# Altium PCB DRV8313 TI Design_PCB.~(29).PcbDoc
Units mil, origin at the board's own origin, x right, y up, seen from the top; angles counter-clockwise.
Board outline 2200 x 1250 mil, 2 copper layers (Top Layer, Bottom Layer), stack 62 mil thick; 47 components, 31 nets, 131 pads, 80 vias.
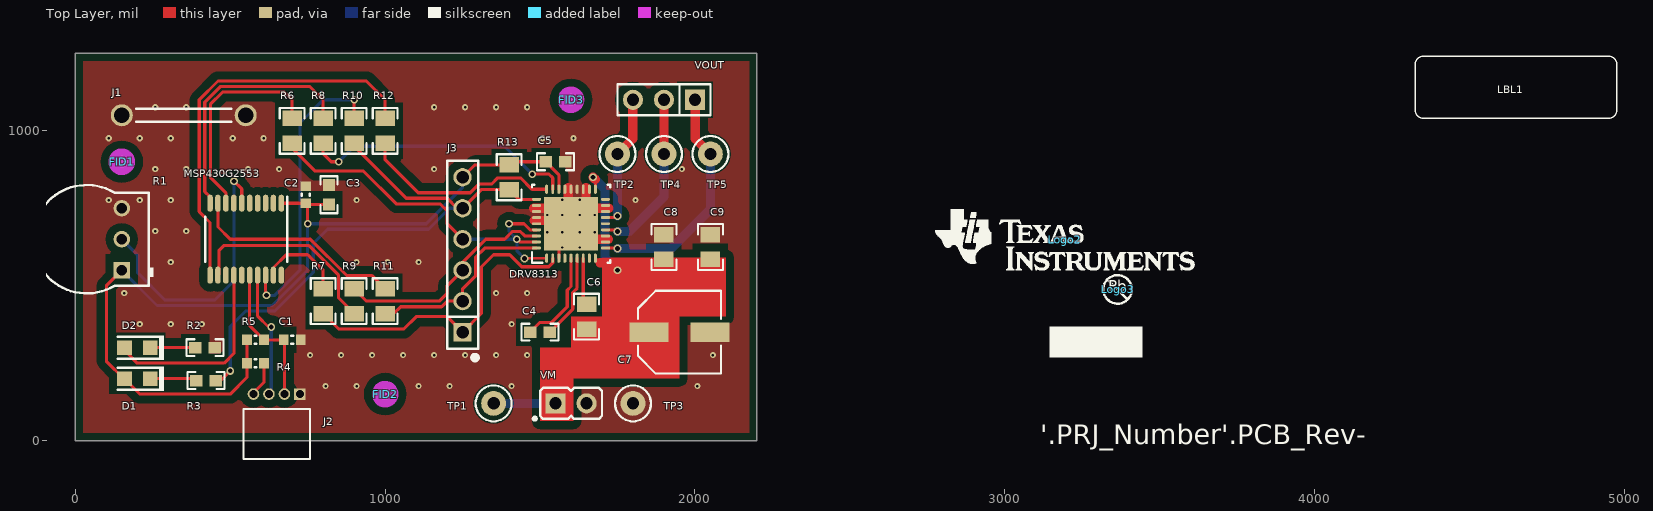
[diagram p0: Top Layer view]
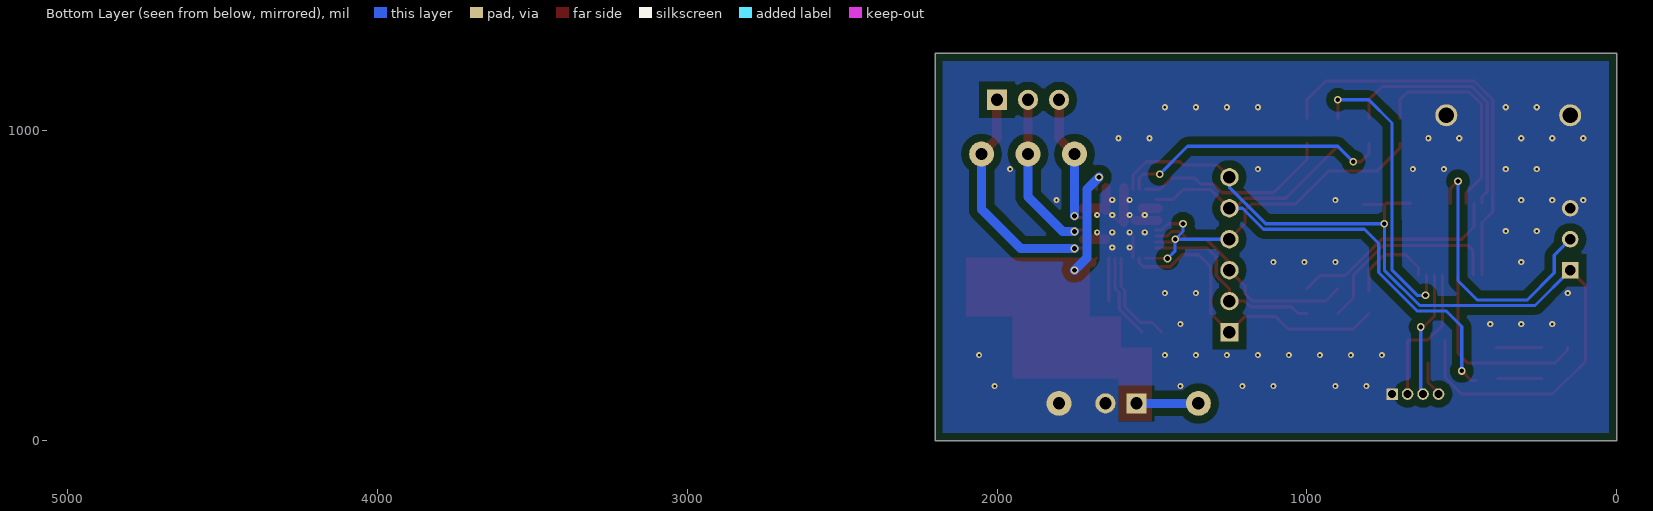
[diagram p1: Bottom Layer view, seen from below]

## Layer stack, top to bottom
Top Solder: solder mask 0.4, Solder Resist, Dk 3.5
Top Layer: signal copper 1.4
Dielectric1: core 59.2, FR-4, Dk 4.8
Bottom Layer: signal copper 1.4
Bottom Solder: solder mask 0.4, Solder Resist, Dk 3.5

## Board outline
0,0 2200,0 2200,1250 0,1250

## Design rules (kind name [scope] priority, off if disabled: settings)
AcuteAngle [All] p1: minimum=4.50000000000000E+0001 checktracksonly=FALSE
AssemblyTestPointUsage [All] p1: valid=2
BoardOutlineClearance BoardOutlineClearance_MountingHoles [OnCopper and InComponentClass('Mounting Holes')] p1: gap=40
BoardOutlineClearance BoardOutlineClearance_Poly [OnCopper and IsPoly] p2: gap=25
BoardOutlineClearance [OnCopper and Not InComponentClass('Logo') and not InComponentClass('FiducialMark') and not InRegion(1000,500,4000,800) and not InPoly] p3: gap=75
Clearance Clearance_Keepouts [((IsTrack Or IsArc) And Not InPoly) And IsFree and IsKeepOut vs ((IsTrack Or IsArc) And Not InPoly) And IsFree and IsKeepOut] p1: gap=0
Clearance Clearance_Poly [InPolygon] p2: gap=25
Clearance [All] p3: gap=7.87
ComponentClearance ComponentClearance_MountingHoles_FiducialMarks [InComponentClass('Mounting Holes') vs InComponentClass('FiducialMark')] p1: gap=50 collisioncheckmode=3 verticalgap=10 showdistances=FALSE
ComponentClearance ComponentClearance_Shunt [InComponentClass('Header') vs InComponentClass('Shunt')] p2: gap=0 collisioncheckmode=3 verticalgap=0 showdistances=FALSE
ComponentClearance ComponentClearance_Logo [InComponentClass('Logo')] p3: gap=50 collisioncheckmode=3 verticalgap=10 showdistances=FALSE
ComponentClearance ComponentClearance_ScrewToNut [(HasFootprint('NY PMS 440 0025 PH')) vs (HasFootprint('Keystone_1902C'))] p4: gap=5 collisioncheckmode=3 verticalgap=10 showdistances=FALSE
ComponentClearance ComponentClearance_MountingHoles [InComponentClass('Mounting Holes')] p5: gap=250 collisioncheckmode=3 verticalgap=100000 showdistances=FALSE
ComponentClearance ComponentClearance_SmallPassives [HasFootprint('0201*') or HasFootprint('0402*') or HasFootprint('0508') or HasFootprint('0603*') or HasFootprint('0612') or HasFootprint('0805*') or HasFootprint('0815*') or HasFootprint('0830*') or HasFootprint('1206*') or HasFootprint('1210*') or HasFootprint('1808*') or HasFootprint('1812*') or HasFootprint('1825*') or HasFootprint('2010*') or HasFootprint('2220*') or HasFootprint('2225*') or HasFootprint('2512*') or HasFootprint('2728*') or HasFootprint('3518*') vs HasFootprint('0201*') or HasFootprint('0402*') or HasFootprint('0508') or HasFootprint('0603*') or HasFootprint('0612') or HasFootprint('0805*') or HasFootprint('0815*') or HasFootprint('0830*') or HasFootprint('1206*') or HasFootprint('1210*') or HasFootprint('1808*') or HasFootprint('1812*') or HasFootprint('1825*') or HasFootprint('2010*') or HasFootprint('2220*') or HasFootprint('2225*') or HasFootprint('2512*') or HasFootprint('2728*') or HasFootprint('3518*')] p6: gap=14.96 collisioncheckmode=3 verticalgap=10 showdistances=FALSE
ComponentClearance ComponentClearance_THtoSMT [IsThruComponent vs IsSMTComponent] p7: gap=40 collisioncheckmode=3 verticalgap=30 showdistances=FALSE
ComponentClearance ComponentClearance_THtoTH [IsThruComponent vs IsThruComponent] p8: gap=30 collisioncheckmode=3 verticalgap=30 showdistances=FALSE
ComponentClearance [All] p9: gap=30 collisioncheckmode=3 verticalgap=10 showdistances=FALSE
DiffPairsRouting [All] p1: maxlimit=100 minlimit=10 mostfreqgap=10 toplayer_minwidth=15 toplayer_maxwidth=15 toplayer_prefwidth=15 bottomlayer_minwidth=15 bottomlayer_maxwidth=15 bottomlayer_prefwidth=15 maxuncoupledlength=1000
FabricationTestPointUsage TestPointUsage [All] p1: valid=2 allowmultiple=FALSE
FabricationTestpoint Testpoint [All] p1: side=3 testpointundercomponent=TRUE minsize=40 maxsize=100 preferedsize=60 minholesize=0 maxholesize=40 preferedholesize=32 testpointgrid=1 allowsidetop=TRUE allowsidebottom=TRUE usegrid=TRUE gridtolerance=0.01
FanoutControl Fanout_LCC [IsLCC] p1: bgadir=Out bgaviamode=Centered fanoutstyle=Auto fanoutdirection=Alternating viagrid=1 // Fanout_LCC (Default Rule)
FanoutControl Fanout_BGA [IsBGA] p2: bgadir=Out bgaviamode=Centered fanoutstyle=Auto fanoutdirection=Alternating viagrid=1 // Fanout_BGA (Default Rule)
FanoutControl Fanout_Default [All] p4: bgadir=Out bgaviamode=Centered fanoutstyle=Auto fanoutdirection=Alternating viagrid=1 // Fanout_Default (Default Rule)
FanoutControl Fanout_Small [(CompPinCount < 5)] p5: bgadir=Out bgaviamode=Centered fanoutstyle=Auto fanoutdirection=OutThenIn viagrid=1 // Fanout_Small (Default Rule)
HoleSize [All] p1: absolutevalues=TRUE maxlimit=251 minlimit=7.87 maxpercent=80.000 minpercent=20.000
MinimumAnnularRing MinimumAnnularRing_ThermalPadVias [IsVia and InAnyComponent] p1: minimumring=5.91
MinimumAnnularRing [All] p2: minimumring=8
MinimumSolderMaskSliver MinimumSolderMaskSliver_Logo [InComponentClass('Logo') vs InComponentClass('Logo')] p1: minsoldermaskwidth=0.7
MinimumSolderMaskSliver [All] p2: minsoldermaskwidth=3.94
PlaneConnect [All] p1: planeconnectstyle=Relief reliefexpansion=10 reliefentries=4 reliefconductorwidth=10 reliefairgap=10
PolygonConnect [All] p1: connectstyle=Direct reliefconductorwidth=10 reliefentries=4 polygonreliefangle="90 Angle" airgapwidth=10
RoutingVias ThermalPadVias [IsVia and InAnyComponent] p1: holewidth=7.87 width=19.68 viastyle="Through Hole" minholewidth=7.87 minwidth=19.68 maxholewidth=12.99 maxwidth=23.62
RoutingVias [All] p2: holewidth=16 width=34 viastyle="Through Hole" minholewidth=7.87 minwidth=26 maxholewidth=40 maxwidth=65
SilkToBoardRegionClearance [Not ((IsComment or IsDesignator) And (Hide <> 'False')) and not InRegion(1000,500,4000,800)] p1:
SilkToSilkClearance SilkToSilkClearance_Pb-FreeLogo [(HasFootprint('Pb-Free_Overlay_Medium') OR HasFootprint('Pb-Free_Overlay_Small')) vs (HasFootprint('Pb-Free_Overlay_Medium') OR HasFootprint('Pb-Free_Overlay_Small'))] p1: silktosilkclearance=0
SilkToSilkClearance [All] p2: silktosilkclearance=4
SilkToSolderMaskClearance SilkToComponentPadClearance [IsPad and InAnycomponent] p1: minsilkscreentomaskgap=5 clearancetoexposedcopper=TRUE
SilkToSolderMaskClearance "Silk to Solder Mask Opening" [All] p2: minsilkscreentomaskgap=4 clearancetoexposedcopper=FALSE
SolderMaskExpansion [All] p1: expansion=1.97
Width [All] p1: maxlimit=100 minlimit=6 preferedwidth=10 checkconnectedcopper=TRUE
15 further rules are at their usual default settings.

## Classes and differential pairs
component class Logo: Logo1
component class FiducialMark: FID1 FID2 FID3
component class AssemblyNote: ZZ1 ZZ2 ZZ3 ZZ4
component class Label: LBL1
component class Header: J3 J? VM VOUT

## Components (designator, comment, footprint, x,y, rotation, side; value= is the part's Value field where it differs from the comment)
C1 "GRM188R71C102KA01D" 0603L 700,325 r0 top (schematic designator C7)
C2 "C0603C104K8RACTU" 0603L 743.68,793.5 r90 top (schematic designator C4)
C3 "GCM188R71C474KA55D" 0603 818.68,793.5 r90 top (schematic designator C9)
C4 "0.01uF" 0603 1500,350 r0 top (schematic designator C6)
C5 "GCM188R71C474KA55D" 0603 1550,900 r0 top (schematic designator C8)
C6 "C2012X5R2A104K125AA" 0805_HV 1650,400 r270 top (schematic designator C2)
C7 "EEE-FK1K100XP" SM_RADIAL_D8 1950,350 r0 top (schematic designator C5)
C8 "C2012X5R2A104K125AA" 0805_HV 1900,625 r270 top (schematic designator C1)
C9 "C2012X5R2A104K125AA" 0805_HV 2050,625 r90 top (schematic designator C2)
D1 "LTST-C170KRKT" LED_LTST-C170_Red 200,200 r0 top
D2 "LTST-C170KGKT" LTST-C170KGKT_Green 200,300 r0 top (schematic designator D3)
DRV8313 "DRV8313RHHR" RHH0036C 1600,700 r90 top (schematic designator U?)
FID1 "Fiducial" Fiducial10-20 150,900 r0 top
FID2 "Fiducial" Fiducial10-20 1000,150 r0 top
FID3 "Fiducial" Fiducial10-20 1600,1100 r0 top
J1 "D3082-05" Harwin_D3082-05 350,1050 r0 top (schematic designator J2)
J2 "851-43-004-20-001000" CONN_851-43-004-20-001000 650,150 r0 top (schematic designator J4)
J3 "PEC06SAAN" Sullins_PEC06SAAN 1250,600 r90 top (schematic designator J5)
LBL1 "Size: 0.65\" x 0.20 \"" Label_650x200 4650,1140.66 r0 top
Logo1 "FCC disclaimer" FCC_disclaimer 2350,3380 r0 top (schematic designator Logo3)
Logo2 "Texas Instruments" TI_Stacked_Overlay_Small 3193.98,647.98 r0 top (schematic designator Logo1)
Logo3 "Pb-Free Symbol" Pb-Free_Overlay_Small 3363.98,487.98 r0 top (schematic designator Logo2)
MSP430G2553 "MSP430G2553IPW20R" PW0020A_N 550,650 r270 top (schematic designator U2)
R1 "3352T-1-503LF" Bourns_3352T 150,650 r90 top (schematic designator R6)
R2 "CRCW0603330RJNEA" 0603 418.5,300 r0 top (schematic designator R3)
R3 "CRCW0603330RJNEA" 0603 421.95,193.68 r0 top (schematic designator R1)
R4 "CRCW06030000Z0EA" 0603L 581.3,250 r180 top (schematic designator R9)
R5 "CRCW060347K0JNEA" 0603L 581.3,325 r180 top (schematic designator R8)
R6 "ERJ-6GEY0R00V" 0805_HV 700,1000 r270 top (schematic designator R7)
R7 "ERJ-6GEY0R00V" 0805_HV 800,450 r270 top (schematic designator R12)
R8 "ERJ-6GEY0R00V" 0805_HV 800,1000 r270 top (schematic designator R16)
R9 "ERJ-6GEY0R00V" 0805_HV 900,450 r90 top (schematic designator R14)
R10 "ERJ-6GEY0R00V" 0805_HV 900,1000 r270 top (schematic designator R5)
R11 "ERJ-6GEY0R00V" 0805_HV 1000,450 r270 top (schematic designator R13)
R12 "ERJ-6GEY0R00V" 0805_HV 1000,1000 r270 top (schematic designator R15)
R13 "CRCW080510K0JNEA" 0805_HV 1400,850 r90 top (schematic designator R4)
TP1 "5000" Keystone5000 1350,120 r0 top
TP2 "5002" Keystone5002 1750,925 r0 top (schematic designator TP17)
TP3 "5001" Keystone5001 1800,120 r0 top (schematic designator TP2)
TP4 "5002" Keystone5002 1900,925 r0 top (schematic designator TP16)
TP5 "5002" Keystone5002 2050,925 r0 top (schematic designator TP15)
VM "PBC02SAAN" Sullins_PBC02SAAN 1600,120 r90 top (schematic designator J?)
VOUT "PBC03SAAN" PBC03SAAN 1900,1100 r180 top (schematic designator J?)
ZZ1 "These assemblies must comply with workmanship standards IPC-A-610 Class 2, unless otherwise specified." AssemblyNote 355,7262 r0 top (schematic designator ZZ4)
ZZ2 "These assemblies must be clean and free from flux and all contaminants. Use of no clean flux is not acceptable." AssemblyNote 355,7350.56 r0 top (schematic designator ZZ3)
ZZ3 "These assemblies are ESD sensitive, ESD precautions shall be observed." AssemblyNote 355,7439.11 r0 top (schematic designator ZZ2)
ZZ4 "This Assembly Note is for PCB labels only" AssemblyNoteLabel 355,7548 r0 top (schematic designator ZZ1)

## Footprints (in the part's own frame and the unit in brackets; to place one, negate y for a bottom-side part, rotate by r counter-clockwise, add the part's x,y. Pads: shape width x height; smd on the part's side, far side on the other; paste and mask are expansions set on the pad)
0603 [mm] "0603 from SM-752 data"
  rect 1x0.95 smd: 1(-0.8,0) 2(0.8,0)
  silkscreen extent -1.52,-0.69 1.52,0.69, body extent -0.87,-0.47 0.87,0.47, height 1
0603L [mm] "0603 from SM-752 data"
  rect 0.8x0.85 smd: 1(-0.7,0) 2(0.7,0)
  silkscreen extent -0.07,-0.33 0.07,0.33, body extent -0.87,-0.47 0.87,0.47, height 1
0805_HV [mil] "0805 with 30mil clearance between pads"
  rect 50x63 smd: 1(-40,0) 2(40,0)
  silkscreen extent -74,-40 74,40, body extent -43,-29 43,29, height 57
AssemblyNote [mil] "Assembly Note"
AssemblyNoteLabel [mil] "Assembly Note for PCB Labels"
Bourns_3352T [mm] "TH, 3-Leads, Body 9.53x8.89mm, Pitch 2.54mm"
  rect 1.35x1.35 hole 0.85: 1(-2.54,0)
  round 1.35 hole 0.85: 2(0,0) 3(2.54,0)
  silkscreen extent -4.44,-2.6 4.44,7.31, body extent -4.44,-2.21 4.45,7.32, height 3.81
CONN_851-43-004-20-001000 [mm] "MILL-MAX"
  rect 0.95x0.95 hole 0.65: 1(1.905,0)
  round 0.95 hole 0.65: 2(0.635,0) 3(-0.635,0) 4(-1.905,0)
  silkscreen extent -2.73,-5.31 2.73,-1.22, body extent -2.73,-5.31 2.73,0.23, height 2.23
FCC_disclaimer [mil]
Fiducial10-20 [mm]
  round 1 smd mask+0.5: 1(0,0)
  Top Layer keep-out circle w1.178: c0,0 r0.5
Harwin_D3082-05 [mm] "Shorting Plug, 10.16mm spacing, TH"
  round 1.8 hole 1.3: 1(-5.08,0) 2(5.08,0)
  silkscreen extent -3.9,-0.53 3.9,0.53, body extent -5.6,-0.52 5.61,0.52, height 6.63
Keystone5000 [mil] "For Keystone 500x miniature loop terminals"
  round 80 hole 40: 1(0,0)
  silkscreen extent -58,-58 58,58, body extent -49,-49 49,49, height 182
Keystone5001 [mil] "For Keystone 500x miniature loop terminals"
  round 80 hole 40: 1(0,0)
  silkscreen extent -58,-58 58,58, body extent -49,-49 49,49, height 182
Keystone5002 [mil] "For Keystone 500x miniature loop terminals"
  round 80 hole 40: 1(0,0)
  silkscreen extent -58,-58 58,58, body extent -49,-49 49,49, height 182
Label_650x200 [mil] "Thermal Transfer Label"
  silkscreen extent -325,-100 325,100, body extent -325,-100 325,100, height 1
LED_LTST-C170_Red [mm] "LITE-ON"
  rect 1.2x1.2 smd: 1(-1.05,0) 2(1.05,0)
  silkscreen extent -1.6,-1 2.2,1, body extent -1.05,-0.67 1.05,0.67, height 1.1
LTST-C170KGKT_Green [mm] "LITE-ON"
  rect 1.2x1.2 smd: 1(-1.05,0) 2(1.05,0)
  silkscreen extent -1.6,-1 2.2,1, body extent -1.05,-0.67 1.05,0.67, height 1.1
Pb-Free_Overlay_Small [mil]
  silkscreen extent -46,-46 46,46
PBC03SAAN [mm] "Sullins 100mil, 1x3, 230 mil above insulator"
  rect 1.65x1.65 hole 1.016: 1(-2.54,0)
  round 1.65 hole 1.016: 2(0,0) 3(2.54,0)
  silkscreen extent -3.81,-1.27 3.81,1.27, body extent -3.81,-1.27 3.81,1.27, height 8.38
PW0020A_N [mm] "TSOP, 20-Leads, Body 6.5x4.4mm, Pitch 0.65mm, IPC Medium Density"
  oval 1.4x0.45 smd: 1(-2.95,2.925) 2(-2.95,2.275) 3(-2.95,1.625) 4(-2.95,0.975) 5(-2.95,0.325) 6(-2.95,-0.325) 7(-2.95,-0.975) 8(-2.95,-1.625) 9(-2.95,-2.275) 10(-2.95,-2.925) 11(2.95,-2.925) 12(2.95,-2.275) 13(2.95,-1.625) 14(2.95,-0.975) 15(2.95,-0.325) 16(2.95,0.325) 17(2.95,0.975) 18(2.95,1.625) 19(2.95,2.275) 20(2.95,2.925)
  silkscreen extent -3.5,-3.3 1.85,3.4, body extent -3.21,-3.25 3.21,3.25, height 1
RHH0036C [mm] "QFN, 36-Leads, Body 6x6mm, Pitch 0.5mm, Thermal Pad 4.4x4.4mm, TI Recommended"
  oval 0.75x0.24 smd: 1(-2.825,2) 2(-2.825,1.5) 3(-2.825,1) 4(-2.825,0.5) 5(-2.825,0) 6(-2.825,-0.5) 7(-2.825,-1) 8(-2.825,-1.5) 9(-2.825,-2) 19(2.825,-2) 20(2.825,-1.5) 21(2.825,-1) 22(2.825,-0.5) 23(2.825,0) 24(2.825,0.5) 25(2.825,1) 26(2.825,1.5) 27(2.825,2)
  oval 0.24x0.75 smd: 10(-2,-2.825) 11(-1.5,-2.825) 12(-1,-2.825) 13(-0.5,-2.825) 14(0,-2.825) 15(0.5,-2.825) 16(1,-2.825) 17(1.5,-2.825) 18(2,-2.825) 28(2,2.825) 29(1.5,2.825) 30(1,2.825) 31(0.5,2.825) 32(0,2.825) 33(-0.5,2.825) 34(-1,2.825) 35(-1.5,2.825) 36(-2,2.825)
  rect 4.4x4.4 smd paste-2.2: 37(0,0)
  silkscreen extent -3.2,-3.2 3.2,3.2, body extent -3.05,-3.05 3.05,3.05, height 1.01
SM_RADIAL_D8 [mm] "6.3 x 7.7mm:  Panasonic D8"
  rect 3.2x1.6 smd: 1(-2.5,0) 2(2.5,0)
  silkscreen extent -3.4,-3.4 3.4,3.4, body extent -3.4,-3.4 3.4,3.4, height 8.01
Sullins_PBC02SAAN [mm] "Sullins 100mil, 1x2, 230 mil above insulator"
  rect 1.65x1.65 hole 1.016: 1(0,1.27)
  round 1.65 hole 1.016: 2(0,-1.27)
  silkscreen extent -1.37,-2.54 1.27,3.1, body extent -1.27,-2.54 1.27,2.54, height 8.38
Sullins_PEC06SAAN [mm] "TH, 6-Leads, Body 608x100mil, Pitch 100mil"
  rect 1.5x1.5 hole 1.016: 1(-6.35,0)
  round 1.5 hole 1.016: 2(-3.81,0) 3(-1.27,0) 4(1.27,0) 5(3.81,0) 6(6.35,0)
  silkscreen extent -8.64,-1.27 7.72,1.27, body extent -7.72,-1.27 7.72,1.27, height 8.59
TI_Stacked_Overlay_Small [mil]
  silkscreen extent -418,-98 418,98

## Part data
C1: "CAP, CERM, 1000 pF, 16 V, +/- 10%, X7R, 0603"
C2: "CAP, CERM, 0.1 µF, 10 V, +/- 10%, X7R, 0603"
C3 C5: "CAP, CERM, 0.47 µF, 16 V, +/- 10%, X7R, AEC-Q200 Grade 1, 0603"
C4: library part Cap, "Capacitor"
C6 C8 C9: "CAP, CERM, 0.1 µF, 100 V, +/- 10%, X5R, 0805"
C7: "CAP, AL, 10 µF, 80 V, +/- 20%, 2.4 ohm, AEC-Q200 Grade 2, SMD"
D1: "LED, Red, SMD"
D2: "LED, Green, SMD"
DRV8313: "2.5-A Triple 1/2-H Bridge Driver, RHH0036C"
FID1 FID2 FID3: "Fiducial mark.  There is nothing to buy or mount."
J1: "1mm Uninsulated Shorting Plug, 10.16mm spacing, TH"
J2: "SOCKET .050\" GRID SIP 4 POS R/A, TH"
J3: "Header, 100mil, 6x1, Tin, TH"
LBL1: library part THT-14-423-10, "Thermal Transfer Printable Labels, 0.650\" W x 0.200\" H - 10,000 per roll"
Logo1: library part FCC_disclaimer, "FCC_disclaimer"
Logo2: library part TI_Logo, "Texas Instrument Corporate Signature"
Logo3: library part Pb-Free
MSP430G2553: "16 MHz Mixed Signal Microcontroller with 16 KB Flash, 512 B SRAM and 24 GPIOs, -40 to 85 degC, 20-pin SOP (PW), Green (RoHS & no Sb/Br)"
R1: "Trimming Potentiometer, 50K, 0.5W, TH"
R2 R3: "RES, 330, 5%, 0.1 W, 0603"
R4: "RES, 0, 5%, 0.1 W, 0603"
R5: "RES, 47 k, 5%, 0.1 W, 0603"
R6 R7 R8 R9 R10 R11 R12: "RES, 0, 5%, 0.125 W, 0805"
R13: "RES, 10 k, 5%, 0.125 W, 0805"
TP1: "Test Point, Miniature, Red, TH"
TP2 TP4 TP5: "Test Point, Miniature, White, TH"
TP3: "Test Point, Miniature, Black, TH"
VM: "Header, 100mil, 2x1, Gold, TH"
VOUT: "Header, 100mil, 3x1, Gold, TH"
ZZ1 ZZ2 ZZ3: library part AssemblyNote
ZZ4: library part AssemblyNoteLabel

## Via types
v1: diameter 19.68, hole 7.87, Top Layer to Bottom Layer, 64 vias
v2: diameter 25, hole 15, Top Layer to Bottom Layer, 16 vias

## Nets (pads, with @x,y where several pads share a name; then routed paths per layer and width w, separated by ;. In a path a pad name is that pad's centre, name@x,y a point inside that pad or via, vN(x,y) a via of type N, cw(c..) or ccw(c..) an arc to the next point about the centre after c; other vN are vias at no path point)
CPH: C4.2 DRV8313.6 | length 275.3
  Top Layer w10: C4.2 1605.63,424.13 1605.63,477.87 1619.68,491.93 DRV8313.6
CPL: C4.1 DRV8313.5 | length 315.3
  Top Layer w10: C4.1 1500.08,381.58 1537.79,381.58 1587.75,431.53 1587.75,485.28 1600,497.53 DRV8313.5
EN: DRV8313.1 DRV8313.33 DRV8313.35 J3.4 R6.2 | length 1255.6
  Top Layer w10: R6.2 700,944.13 774.39,869.74 930.26,869.74 1035.75,764.25 1177.25,764.25 1200,741.5 1200,700 J3.4 ; v2(1400,700) 1448.08,700 1467.77,680.31 DRV8313.33 ; v2(1425,650) 1434.06,640.94 DRV8313.35 ; v2(1450,587.82) DRV8313.1
  Bottom Layer w10: J3.4 v2(1425,650) ; v2(1400,700) 1400,675 v2(1425,650) ; v2(1450,587.82) 1425,612.82 v2(1425,650)
GND: C1.2 C2.2 C3.2 C5.2 C7.2 C8.1 C9.2 DRV8313.3 DRV8313.11 DRV8313.12 DRV8313.16 DRV8313.17 DRV8313.20 DRV8313.21 DRV8313.22 DRV8313.23 DRV8313.24 DRV8313.29 DRV8313.30 DRV8313.31 DRV8313.32 DRV8313.37 J1.1 J1.2 J2.1 MSP430G2553.20 R1.3 R2.2 TP3.1 VM.2 | length 586.5
  Top Layer w10: DRV8313.3 DRV8313.37@1560.63,660.63 ; DRV8313.37 v1(1628.15,728.15) DRV8313.37@1659.06,759.06
  Top Layer w30: 1479.92,750 DRV8313.37@1532.09,750 ; 1480.3,710.57 DRV8313.37@1552.15,710.57 ; DRV8313.37@1590.89,704.44 1590.89,815.66 ; DRV8313.37@1648.23,650 1720.08,650 ; DRV8313.37@1648.48,743.81 1648.48,815.66 ; DRV8313.37@1669.31,750 1721.47,750
  other v1: 808,176 908,176 1108,176 1208,176 1408,176 2008,176 758,276 858,276 958,276 1058,276 1158,276 1258,276 1358,276 1458,276 2058,276 208,376 308,376 408,376 1408,376 158,476 1358,476 1458,476 308,576 908,576 1008,576 1108,576 1571.85,623.23 1628.15,623.23 1523.23,671.85 1571.85,671.85 1628.15,671.85 1676.77,671.85 258,676 358,676 1523.23,728.15 1571.85,728.15 1676.77,728.15 108,776 208,776 308,776 908,776 1808,776 1571.85,776.77 1628.15,776.77 258,876 358,876 558,876 658,876 1158,876 1958,876 108,976 208,976 308,976 508,976 608,976 1508,976 1608,976 258,1076 358,1076 1158,1076 1258,1076 1358,1076 1458,1076
IN1: DRV8313.2 J3.1 R7.2 | length 1026.8
  Top Layer w10: R7.2 850,360 1060,360 1100,400 1200,400 J3.1 1310.28,410.28 1310.28,560.28 1350,600 1401.94,600 1440.8,561.14 1528.55,561.14 1540.94,573.54 DRV8313.2
IN2: DRV8313.36 J3.2 R11.2 | length 634.9
  Top Layer w10: R11.2 1027.87,410 1050,432.13 1182.27,432.13 1200.15,450 J3.2 1250,490.04 1292.4,532.44 1292.4,592.4 1321.26,621.26 DRV8313.36
IN3: DRV8313.34 J3.3 R9.2 | length 734.2
  Top Layer w10: R9.2 940,450 1174.87,450 1200,475.13 1200,500 J3.3 1250,575.28 1324.72,650 1385.88,650 1411.26,675.37 1435.51,675.37 1450.25,660.63 DRV8313.34
NetD1_2: D1.2 R3.1 | length 142.8
  Top Layer w10: D1.2 R3.1@384.13,200
NetD3_2: D2.2 R2.1 | length 148.6
  Top Layer w10: D2.2 R2.1 R2.1@389.96,300
NetJ4_4: J2.4 R4.1 | length 114
  Top Layer w10: J2.4 575,153.98 608.86,187.84 R4.1
NetR5_1: MSP430G2553.18 R10.1 | length 948.5
  Top Layer w10: MSP430G2553.18 613.98,472.18 v2(617.24,468.91) ; R10.1 v2(900,1100)
  Bottom Layer w10: v2(617.24,468.91) 643.63,468.91 724.63,549.9 724.63,710.86 724.98,711.22 724.98,1024.98 800,1100 v2(900,1100)
NetR7_1: MSP430G2553.8 R6.1 | length 690.7
  Top Layer w10: MSP430G2553.8 486.02,799.58 435.75,849.85 435.75,1085.19 475.28,1124.72 675.28,1124.72 700,1100 R6.1
NetR15_1: MSP430G2553.11 R12.1 | length 1290.7
  Top Layer w10: MSP430G2553.11 434.84,703.98 400,738.82 400,1100 460.47,1160.47 939.53,1160.47 1000,1100 R12.1
NetR16_1: MSP430G2553.10 R8.1 | length 814
  Top Layer w10: MSP430G2553.10 434.84,786.57 417.87,803.54 417.87,1092.6 467.87,1142.6 757.4,1142.6 800,1100 R8.1
NFAULT: DRV8313.28 J3.5 R3.2 R10.2 R13.1 | length 1875.2
  Top Layer w10: R3.2 468.68,193.68 v2(500,225) ; R10.2@900,950 1067.87,782.13 1200,782.13 1232.13,750 J3.5 1310,810 R13.1 1431.26,778.74 DRV8313.28
  Bottom Layer w10: v2(500,225) 500,368.28 550,418.28 643.56,418.28 767.87,542.6 767.87,636.16 813.84,682.13 1140.04,682.13 1207.92,750 J3.5
NRESET: DRV8313.26 R8.2 | length 885.6
  Top Layer w10: R8.2 800,926 826,900 v2(850,900) ; v2(1475,860) 1529.13,860 1540.94,848.19 DRV8313.26
  Bottom Layer w10: v2(850,900) 900,950 1385,950 v2(1475,860)
NSLEEP: DRV8313.27 R12.2 | length 653.9
  Top Layer w10: R12.2 1000,906.5 1106.5,800 1274.72,800 1302.6,827.87 1343.17,827.87 1363.17,847.87 1436.83,847.87 1473.49,811.22 DRV8313.27
OUT1: DRV8313.10 TP5.1 VOUT.1 | length 764.5
  Top Layer w10: DRV8313.10 1748.74,621.26 v2(1750,620)
  Top Layer w30: VOUT.1@2001,1099 2001,974 TP5.1
  Bottom Layer w30: v2(1750,620) 1923.54,620 2050,746.46 TP5.1
OUT2: DRV8313.13 TP4.1 VOUT.2 | length 550.3
  Top Layer w10: DRV8313.13 1744.69,680.31 v2(1750,675)
  Top Layer w30: TP4.1 VOUT.2
  Bottom Layer w30: v2(1750,675) 1787.82,675 1900,787.18 TP4.1
OUT3: DRV8313.15 TP2.1 VOUT.3 | length 435.3
  Top Layer w10: DRV8313.15 1744.68,719.68 v2(1750,725)
  Top Layer w30: TP2.1 1799.04,974.04 VOUT.3@1799.04,1099.04
  Bottom Layer w30: v2(1750,725) TP2.1
POT: MSP430G2553.6 R1.2 | length 905.6
  Top Layer w10: v2(512.28,837.47) 537.2,812.55 MSP430G2553.6
  Bottom Layer w10: R1.2 201.57,598.43 201.57,541.22 288.76,454.03 450,454.03 512.28,516.31 v2(512.28,837.47)
PUSH: MSP430G2553.7
PWMA: MSP430G2553.19 R7.1 | length 291
  Top Layer w10: MSP430G2553.19 639.57,558.56 681,600 750,600 800,550 R7.1 R7.1@800,482.06
PWMB: MSP430G2553.9 R11.1 | length 698.8
  Top Layer w10: MSP430G2553.9 460.43,689.57 500,650 758.78,650 875.28,533.5 956.5,533.5 R11.1
PWMC: MSP430G2553.12 R9.1 | length 658.7
  Top Layer w10: MSP430G2553.12 464.29,537.72 464.29,614.29 480.31,630.31 753.19,630.31 850,533.5 850,460 R9.1
RESET: C1.1 J2.2 MSP430G2553.16 R5.1 | length 467.6
  Top Layer w10: MSP430G2553.16 562.8,371.06 R5.1 C1.1 675,322.44 J2.2
STATUS: D2.1 MSP430G2553.14 | length 644.2
  Top Layer w10: D2.1 158.66,291.34 200,250 480.26,250 511.61,281.36 MSP430G2553.14
TEST: J2.3 MSP430G2553.17 | length 410.5
  Top Layer w10: MSP430G2553.17 588.39,401.88 623.53,366.73 v2(632.52,366.73)
  Bottom Layer w10: J2.3 632.52,157.52 v2(632.52,366.73)
V3P3: C2.1 C3.1 C5.1 D1.1 DRV8313.25 J3.6 MSP430G2553.1 R1.1 R4.2 R5.2 R13.2 | length 2992.8
  Top Layer w10: R1.1 100,500 100,256 D1.1@158.66,197.34 ; D1.1 208.66,150 500,150 553.74,203.74 R4.2 R5.2 ; MSP430G2553.1 743.48,766.14 C2.1 747.62,762.01 C3.1 ; v2(750,700) C2.1@750,759.63 ; J3.6 1290,890 R13.2 1410,900 C5.1 1560.63,857.87 DRV8313.25
  Bottom Layer w10: R1.1 263.84,436.16 636.16,436.16 750,550 v2(750,700) 1132.64,700 1250,817.36 J3.6
VCP: C6.1 DRV8313.7 | length 138.1
  Top Layer w10: C6.1@1639.37,450.63 DRV8313.7
VM: C6.2 C7.1 C8.2 C9.1 DRV8313.9 DRV8313.19 TP1.1 VM.1 | length 620.6
  Top Layer w10: DRV8313.9 1693.5,574.02 ; DRV8313.19 v2@1678.74,842.46
  Top Layer w30: v2(1670.98,850.22) v2@1678.74,842.46 ; 1693.5,574.02 1718.11,574.02
  Bottom Layer w30: TP1.1 VM.1 ; v2(1670.98,850.22) 1709.65,811.54 1709.65,590.35 v2(1750,550)
pads on no net: DRV8313.4 DRV8313.8 DRV8313.14 DRV8313.18 FID1.1 FID2.1 FID3.1 MSP430G2553.2 MSP430G2553.3 MSP430G2553.4 MSP430G2553.5 MSP430G2553.13 MSP430G2553.15

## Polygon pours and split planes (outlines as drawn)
GND on Top Layer "TOP_LAYER_GND_P002" (solid, remove dead copper, pour order 2): 5.51,1.89 2200,1.89 2200,1251.89 5.51,1251.89
GND on Bottom Layer "BOTTOM_LAYER_GND_P008" (solid, remove dead copper, pour order 8): 0,0 2200,0 2200,1250 0,1250

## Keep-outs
Keep-Out Layer:
  text ".Layer_Name" at 577,-858.49 h60

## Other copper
Top Layer:
  rectangle net VM: 1600,200 1950,400
  rectangle net VM: 1500,62.52 1607.48,300
  rectangle net VM: 1700,400 2100,590.55
  text ".Layer_Name" at 577,-858.49 h60
Bottom Layer:
  text ".Layer_Name" at 577,-858.49 h60

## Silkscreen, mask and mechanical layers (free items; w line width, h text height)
Top Overlay:
  region: 3443.98,367.98 3143.98,367.98 3143.98,267.98 3443.98,267.98
  text "This document can handle board shapes up to 7.9in x 10in, although" at 0,6345 h60
  text "our panel vendors top out at 7in x 10in." at 0,6220.94 h60
  text "To re-size the board shape, do the following:" at 55,6096.88 h60
  text "Select lines on M1 Board Outline and delete (easy in single layer mode...shift+s)" at 115,5972.82 h60
  text "Draw a rectangle using lines (example will be for a 4\" x 6\" board" at 115,5848.76 h60
  text "Enter Place Line mode (keyboard pl)" at 325,5724.71 h60
  text "keyboard jo to jump to origin, hit enter" at 325,5600.65 h60
  text "keyboard jl to jump to location, set x to 6000, hit enter twice" at 325,5476.59 h60
  text "keyboard jl to jump to location, set x to 6000 and y to 4000, hit enter twice" at 325,5352.53 h60
  text "keyboard jl to jump to location, set x to 0 and y to 4000, hit enter twice" at 325,5228.47 h60
  text "keyboard jo to jump to origin, hit enter" at 325,5104.41 h60
  text "Hit ESC twice to exit place line mode" at 325,4980.35 h60
  text "Select lines on M1 Board Outline" at 115,4836.3 h60
  text "Menu Design|Board Shape|Define from Selected Objects (keyboard dsd)" at 115,4732.24 h60
  text "If you re-size the board, don't forget to move the drill table strings on the" at 0,4413 h60
  text "Drill Drawing Layer...they should be just to the right of your board shape" at 193,4307 h60
  text "'.PRJ_Number'.PCB_Rev-" at 3113.98,-32.02 h108.27
  text ".Layer_Name" at 577,-858.49 h60
Bottom Overlay:
  text ".Layer_Name" at 577,-858.49 h60
Top Paste:
  text ".Layer_Name" at 577,-858.49 h60
Bottom Paste:
  text ".Layer_Name" at 577,-858.49 h60
Top Solder:
  text ".Layer_Name" at 577,-858.49 h60
  text ".Layer_Name" at 577,-858.49 h60
Bottom Solder:
  text ".Layer_Name" at 577,-858.49 h60
Drill Guide:
  text ".Layer_Name" at 577,-858.49 h60
M1 Board Outline:
  lines w10: 0,0 2200,0 ; 0,0 0,1250 ; 0,0 2200,0 ; 0,0 0,1250 ; 0,1250 2200,1250 ; 0,1250 2200,1250 ; 2200,0 2200,1250 ; 2200,0 2200,1250
  text ".Layer_Name" at 577,-858.49 h60
M2 Board Dimensions:
  rectangle: 0,-275 125,-150
  rectangle: 125,-400 500,-275
  lines w7: 0,-275 1000,-275 ; 125,-400 125,-150 ; 250,-400 250,-150 ; 500,-400 500,-150 ; 750,-400 750,-150 ; 0,-400 1000,-400 1000,-150 0,-150 0,-400
  text ".Layer_Name" at 577,-858.49 h60
M3 3D STEP Top:
  text ".Layer_Name" at 577,-858.49 h60
M4 3D STEP Bottom:
  text ".Layer_Name" at 577,-858.49 h60
M5 Assembly Top:
  lines w10: -292,-930.17 6308,-930.17 ; -292,-726.83 6310,-726.83 ; -292,-523.5 -292,-1133.5 3713,-1133.5 6310,-1133.5 6310,-523.5 -291.5,-523.5 -291.5,-1133.5 1284,-1133.5 ; 2173,-1133.5 2173,-523.5 ; 3440,-726.83 3440,-523.5 ; 4280,-726.83 4280,-523.5 ; 4902,-1140 4902,-937.17
  text "COMPONENTS MARKED 'DNP' SHOULD NOT BE POPULATED." at 1153.5,-318.5 h60
  text "ASSEMBLY VARIANT:" at 1153,-434 h60
  text ".VariantName" at 2189,-434 h60
  text "PCB VIEWED FROM TOP SIDE" at -228.5,-655.67 h60
  text "BOARD #:" at 2248,-655.67 h60
  text ".PRJ_Number" at 2793.5,-655.67 h60
  text "REV:" at 3638,-655.67 h60
  text ".PCB_Rev" at 3929.5,-655.67 h60
  text "SVN REV:" at 4476,-655.67 h60
  text ".VersionControl_RevNumber" at 4982,-655.67 h60
  text "TID #:" at 2248,-859 h60
  text ".TID" at 2793.5,-859 h60
  text "PLOT NAME =" at -228.5,-1064.34 h60
  text ".plot_File_Name" at 577,-1064.34 h60
  text "GENERATED    :" at 2250,-1064.34 h60
  text ".Print_Date" at 3119.5,-1064.34 h60
  text ".Print_Time" at 3848.5,-1064.34 h60
  text "TEXAS INSTRUMENTS" at 5113,-1064.34 h60
M6 Assembly Bottom:
  lines w10: -292.5,-727.33 6309.5,-727.33 ; -290.5,-930.67 6309.5,-930.67 ; 1115.5,-1140.5 1115.5,-937.67 ; 1737.5,-727.33 1737.5,-524 ; 2577.5,-727.33 2577.5,-524 ; 3844.5,-1134 3844.5,-524 ; 4733.5,-1134 6309,-1134 6309,-524 -292.5,-524 -292.5,-1134 2304.5,-1134 6309.5,-1134 6309.5,-524
  text "COMPONENTS MARKED 'DNP' SHOULD NOT BE POPULATED." at 6102,-318 h60
  text ".VariantName" at 5058,-434 h60
  text "ASSEMBLY VARIANT:" at 6097,-434 h60
  text ".VersionControl_RevNumber" at 1035.5,-656.17 h60
  text "SVN REV:" at 1541.5,-656.17 h60
  text ".PCB_Rev" at 2088,-656.17 h60
  text "REV:" at 2379.5,-656.17 h60
  text ".PRJ_Number" at 3224,-656.17 h60
  text "BOARD #:" at 3769.5,-656.17 h60
  text "PCB VIEWED FROM BOTTOM SIDE" at 6246,-656.17 h60
  text ".TID" at 3224,-859.5 h60
  text "TID #:" at 3769.5,-859.5 h60
  text "TEXAS INSTRUMENTS" at 904.5,-1064.84 h60
  text ".Print_Time" at 2169,-1064.84 h60
  text ".Print_Date" at 2898,-1064.84 h60
  text "GENERATED    :" at 3767.5,-1064.84 h60
  text ".plot_File_Name" at 5440.5,-1064.84 h60
  text "PLOT NAME =" at 6246,-1064.84 h60
M9 Title Sheet:
  drawing of 57 lines, arcs and shapes, not listed
  text "1" at 739.84,8036.5 h70
  text "2" at 3235.5,8036.5 h70
  text "3" at 5724.84,8036.5 h70
  text "4" at 8231.51,8036.5 h70
  text "5" at 10730.5,8036.5 h70
  text "6" at 13235.5,8036.5 h70
  text "A" at -416.5,6893.5 h70
  text "A" at 14383.5,6893.5 h70
  text "B" at -416.5,4513.5 h70
  text "B" at 14383.5,4513.5 h70
  text "C" at -416.5,2138.5 h70
  text "C" at 14383.5,2138.5 h70
  text "PROJECT TITLE:" at 11343.5,277.5 h45
  text ".PRJ_Title" at 11393.5,144.17 h70
  text "DESIGNED FOR:" at 11343.5,-23.5 h45
  text ".PRJ_Customer" at 11393.5,-163.5 h70
  text "D" at -416.5,-231.5 h70
  text "D" at 14383.5,-231.5 h70
  text "FILE NAME:" at 11343.5,-323.5 h45
  text ".PCB_File_Name_No_Path" at 11393.5,-443.5 h70
  text "Texas Instruments (TI) and/or its licensors do not warrant the accuracy or completeness of this specification" at 6374,-605.34 h45
  text "ENGINEER:" at 11343.5,-613.5 h45
  text "LAYOUT BY:" at 12848.5,-613.5 h45
  text "or any information contained therein. TI and/or its licensors do not warrant that this design will meet" at 6329.01,-718 h45
  text ".PRJ_Engineer" at 11393.5,-768.49 h70
  text ".PCB_Layout" at 12899,-768.49 h70
  text "the specifications, will be suitable for your application or fit for any particular purpose, or will operate in" at 6329.01,-830.67 h45
  text ".Layer_Name" at 577,-858.49 h60
  text "ALTIUM DESIGNER VERSION:" at 12848.5,-923.5 h45
  text "an implementation. TI and/or its licensors do not warrant that the design is production worthy. You should" at 6329.01,-943.33 h45
  text "completely validate and test your design implementation to confirm the system functionality for your application." at 6374,-1056 h45
  text ".print_Scale" at 11393.5,-1056.83 h70
  text ".Application_BuildNumber" at 12899,-1056.83 h70
  text "1" at 739.84,-1263.5 h70
  text "2" at 3235.5,-1263.5 h70
  text "3" at 5724.84,-1263.5 h70
  text "4" at 8231.51,-1263.5 h70
  text "5" at 10730.5,-1263.5 h70
  text "6" at 13235.5,-1263.5 h70
M10 Fab Notes:
  drawing of 173 lines, arcs and shapes, not listed
  text "DESIGN INFORMATION" at 12378.02,6201 h60
  text "MIN. TRACK WIDTH:" at 11733.46,6021 h60
  text "8" at 12829.7,6021 h60
  text "MIL" at 12984.46,6021 h60
  text "MIN. CLEARANCE:" at 11733.46,5889 h60
  text "0.2" at 12769.7,5889 h60
  text "mm" at 12984.46,5889 h60
  text "MIN. VIA PAD SIZE:" at 11733.46,5757 h60
  text "24" at 12799.71,5757 h60
  text "MIL" at 12984.46,5757 h60
  text "0.05mm (2MIL)" at 12428.46,5615.29 h60
  text "MINIMUM ANNULAR RING" at 11404.23,5611 h60
  text "EXTERNAL" at 13136.46,5611 h60
  text "PER" at 11604.23,5493 h60
  text "IPC-D-275 CLASS 2 LEVEL C" at 11824.23,5493 h60
  text "MIL, HOLES" at 13312.46,5380.71 h60
  text "+/-" at 12920,5380 h60
  text "+/-" at 13774,5380 h60
  text "REGISTRATION TOLERANCES:" at 11404.23,5375 h60
  text "METAL" at 12604,5375 h60
  text "5" at 13180.2,5375 h60
  text "3" at 14013.2,5375 h60
  text "MIL" at 14129.46,5375 h60
  text "+/-" at 13774,5262 h60
  text "HOLE SIZE TOLERANCE (UNLESS OTHERWISE SPECIFIED):" at 11404.23,5257 h60
  text "3" at 14013.2,5257 h60
  text "MIL" at 14129.46,5257 h60
  text "MATERIAL:" at 11329.46,5047.54 h60
  text "FR-4 High Tg" at 12315.9,4907.21 h60
  text "FR-408" at 11750.46,4898.64 h60
  text "OTHER" at 13238.46,4898.64 h60
  text "X" at 12161,4895 h60
  text "62 MIL (1.6mm) +/-10%" at 12070.56,4735.92 h60
  text "THICKNESS:" at 11404.23,4731.64 h60
  text "X" at 11942.4,4731.64 h60
  text "OTHER" at 13355.46,4731.64 h60
  text "TOLERANCE:" at 11404.23,4573.64 h60
  text "X" at 12243.53,4573.64 h60
  text "ANSI IPC-6012 TYPE 3 CLASS 2" at 12430.48,4573.64 h60
  text "OTHER +/-" at 12430.46,4417.64 h60
  text "BOW & TWIST:" at 11404.23,4260.64 h60
  text "X" at 12243.53,4260.64 h60
  text "ANSI IPC-6012 TYPE 3 CLASS 2" at 12430.48,4260.64 h60
  text "OTHER +/-" at 12430.46,4102.13 h60
  text "DRILLING:" at 11329.46,3963.64 h60
  text "REFERENCE:" at 11404.23,3846.64 h60
  text "X" at 12052.46,3846.64 h60
  text "AS SHOWN" at 12239.46,3846.64 h60
  text "X" at 12953.46,3846.64 h60
  text "NC_DRILL FILES" at 13090.46,3846.64 h60
  text "PTH COPPER THICKNESS:" at 11404.23,3688.64 h60
  text "X" at 12534.46,3688.64 h60
  text "20-30 um" at 12671.46,3688.64 h60
  text "OTHER" at 13388.46,3688.64 h60
  text "BOARD FINISH:" at 11329.46,3529.64 h60
  text "SILKSCREEN:" at 11484.68,3411.64 h60
  text "X" at 12433.46,3411.64 h60
  text "TOP" at 12559.46,3411.64 h60
  text "X" at 12943.46,3411.64 h60
  text "BOTTOM" at 13070.46,3411.64 h60
  text "SILKSCREEN COLOR:" at 11484.68,3244.64 h60
  text "X" at 12432.42,3244.64 h60
  text "WHITE" at 12559.46,3244.64 h60
  text "OTHER" at 13070.46,3244.64 h60
  text "X" at 12563.42,3085.44 h60
  text "GREEN" at 12690.46,3085.44 h60
  text "OTHER" at 13308.46,3085.44 h60
  text "SOLDER RESIST COLOR:" at 11484.68,3074.64 h60
  text "X" at 12563.42,2915.44 h60
  text "MATTE" at 12690.46,2915.44 h60
  text "SEMI-GLOSS" at 13308,2914.8 h60
  text "IMMERSION GOLD (ENIG)" at 12390.46,2726.92 h60
  text "ENEPIG" at 13728,2723.64 h60
  text "SURFACE FINISH:" at 11329.46,2722.64 h60
  text "X" at 12203.51,2722.64 h60
  text "IMM. TIN/SILVER OR EQUIV" at 11659,2565.64 h60
  text "OTHER" at 13090.46,2565.64 h60
  text "ARRAY/PANEL:" at 11329.46,2386.64 h60
  text "CUT AND TRIM PER M1 BOARD OUTLINE" at 12390.46,2382.35 h60
  text "N.C. ROUTE" at 12390.46,2230.64 h60
  text "X" at 13069.46,2230.64 h60
  text "V. SCORE" at 13256.46,2230.64 h60
  text "CERTIFICATION:" at 11329.46,2093.64 h60
  text "MATERIALS AND WORKMANSHIP FOR ALL PCBS" at 12054.46,2093.64 h60
  text "TO MEET OR EXCEED THE REQUIREMENTS OF:" at 12054.46,1995.64 h60
  text "X" at 11680.96,1859.13 h60
  text "ANSI IPC-A-600F CLASS ->" at 11819.96,1859.13 h60
  text "X" at 13459.02,1859.13 h60
  text "2" at 13577.96,1859.14 h60
  text "1" at 13262.96,1857.64 h60
  text "3" at 13931.96,1857.64 h60
  text "X" at 12495.02,1699.64 h60
  text "RoHS" at 12631.96,1699.64 h60
  text "OTHER" at 13276.36,1699.64 h60
  text "PER ORDER" at 13673.42,1699.64 h60
  text "ALL BOARDS MUST MEET OR EXCEED UL94-V0 REQUIREMENTS." at 11357,1534 h60
  text "PCB MUST BEAR THE UL94V-0 UL REGISTERED MATERIAL ID NUMBER" at 11357,1414 h60
  text "ADDITIONAL REQUIREMENTS:" at 11329.46,1240.64 h60
  text "MICROSECTION:" at 11404.23,1125.64 h60
  text "YES" at 12309.96,1125.64 h60
  text "REQUIRED" at 13171.46,969.49 h60
  text "BARE BOARD ELEC. TEST:" at 11404.23,966.64 h60
  text "NONE" at 12709.96,966.64 h60
  text "X" at 13044.46,966.64 h60
  text "PER ORDER" at 13763.46,966.64 h60
  text ".Layer_Name" at 577,-858.49 h60
M11 Gerber Information:
  lines w10: -292,-930.17 6308,-930.17 ; -292,-726.83 6310,-726.83 ; -292,-523.5 -292,-1133.5 3713,-1133.5 6310,-1133.5 6310,-523.5 -291.5,-523.5 -291.5,-1133.5 1284,-1133.5 ; 2173,-1133.5 2173,-523.5 ; 3440,-726.83 3440,-523.5 ; 4280,-726.83 4280,-523.5 ; 4902,-1140 4902,-937.17
  text "ALL ARTWORK VIEWED FROM TOP SIDE" at -228.5,-655.67 h60
  text "BOARD #:" at 2248,-655.67 h60
  text ".PRJ_Number" at 2793.5,-655.67 h60
  text "REV:" at 3638,-655.67 h60
  text ".PCB_Rev" at 3929.5,-655.67 h60
  text "SVN REV:" at 4476,-655.67 h60
  text ".VersionControl_RevNumber" at 4982,-655.67 h60
  text "LAYER NAME =" at -228.5,-858.49 h60
  text "TID #:" at 2248,-859 h60
  text ".TID" at 2793.5,-859 h60
  text "PLOT NAME =" at -228.5,-1064.34 h60
  text ".plot_File_Name" at 577,-1064.34 h60
  text "GENERATED    :" at 2250,-1064.34 h60
  text ".Print_Date" at 3119.5,-1064.34 h60
  text ".Print_Time" at 3848.5,-1064.34 h60
  text "TEXAS INSTRUMENTS" at 5113,-1064.34 h60
M12 Stackup:
  drawing of 191 lines, arcs and shapes, not listed
  text "Layer" at 9790.34,7830 h60
  text "Name" at 10200.26,7830 h60
  text "Material" at 11130,7830 h60
  text "Thickness" at 11989.77,7830 h60
  text "Constant" at 12639.6,7830 h60
  text "Board Layer Stack" at 13209.46,7830 h60
  text "1" at 9790.34,7710 h60
  text "Top Overlay" at 10200.26,7710 h60
  text "2" at 9790.34,7590 h60
  text "Top Solder" at 10200.26,7590 h60
  text "Solder Resist" at 11130,7590 h60
  text "0.40mil" at 11989.77,7590 h60
  text "3.5" at 12639.6,7590 h60
  text "3" at 9790.34,7470 h60
  text "Top Layer" at 10200.26,7470 h60
  text "Copper" at 11130,7470 h60
  text "1.40mil" at 11989.77,7470 h60
  text "4" at 9790.34,7350 h60
  text "Dielectric1" at 10200.26,7350 h60
  text "FR-4" at 11130,7350 h60
  text "59.20mil" at 11989.77,7350 h60
  text "4.8" at 12639.6,7350 h60
  text "5" at 9790.34,7230 h60
  text "Bottom Layer" at 10200.26,7230 h60
  text "Copper" at 11130,7230 h60
  text "1.40mil" at 11989.77,7230 h60
  text "6" at 9790.34,7110 h60
  text "Bottom Solder" at 10200.26,7110 h60
  text "Solder Resist" at 11130,7110 h60
  text "0.40mil" at 11989.77,7110 h60
  text "3.5" at 12639.6,7110 h60
  text "7" at 9790.34,6990 h60
  text "Bottom Overlay" at 10200.26,6990 h60
  text ".Layer_Name" at 577,-858.49 h60
M13 Component Bodies Top:
  text ".Layer_Name" at 577,-858.49 h60
M14 Component Bodies Bottom:
  text ".Layer_Name" at 577,-858.49 h60
M15 Courtyards Top:
  text ".Layer_Name" at 577,-858.49 h60
M16 Courtyards Bottom:
  text ".Layer_Name" at 577,-858.49 h60
Drill Drawing:
  lines w10: 5336.09,2630.87 5349.9,2630.87 5363.72,2617.06 5377.53,2630.87 5391.34,2630.87 5377.53,2644.68 5391.34,2658.5 5377.53,2658.5 5363.72,2672.31 5349.9,2658.5 5336.09,2658.5 5349.9,2644.68 5336.09,2630.87 ; 5336.09,2796.63 5391.34,2796.63 5363.72,2741.38 5336.09,2796.63 ; 5336.09,2879.51 5349.9,2879.51 5349.9,2865.7 5377.53,2865.7 5377.53,2879.51 5391.34,2879.51 5391.34,2907.14 5377.53,2907.14 5377.53,2920.95 5349.9,2920.95 5349.9,2907.14 5336.09,2907.14 5336.09,2879.51 ; 5336.09,2990.02 5363.72,3003.83 5391.34,2990.02 5377.53,3017.64 5391.34,3045.27 5363.72,3031.46 5336.09,3045.27 5349.9,3017.64 5336.09,2990.02 ; 5336.09,3114.34 5336.09,3128.15 5349.9,3141.96 5336.09,3155.78 5336.09,3169.59 5349.9,3169.59 5363.72,3155.78 5377.53,3169.59 5391.34,3169.59 5391.34,3155.78 5377.53,3141.96 5391.34,3128.15 5391.34,3114.34 5377.53,3114.34 5363.72,3128.15 5349.9,3114.34 5336.09,3114.34 ; 5336.09,3238.66 5391.34,3238.66 5391.34,3293.91 5336.09,3293.91 5336.09,3238.66
  lines w12: 5286,2579.76 8517.49,2579.76 ; 5286,3325.68 8517.49,3325.68 ; 5623.86,2455.44 5623.86,3450 ; 5955.86,2455.44 5955.86,3450 ; 6592.43,2455.44 6592.43,3450 ; 6851.57,2455.44 6851.57,3450 ; 7226.72,2455.44 7226.72,3450 ; 7951.05,2455.44 7951.05,3450 ; 5286,2455.44 8517.49,2455.44 8517.49,3450 5286,3450 5286,2455.44
  text "Symbol" at 5360.59,3362.98 h72
  text "Quantity" at 5661.16,3362.98 h72
  text "Finished Hole Size" at 5993.16,3362.98 h72
  text "Plated" at 6629.72,3362.98 h72
  text "Hole Type" at 6888.86,3362.98 h72
  text "Drill Layer Pair" at 7264.02,3362.98 h72
  text "Hole Tolerance" at 7988.35,3362.98 h72
  text "64" at 5661.16,3238.66 h60
  text "7.87mil (0.200mm)" at 5993.16,3238.66 h60
  text "PTH" at 6629.72,3238.66 h60
  text "Round" at 6888.86,3238.66 h60
  text "Top Layer - Bottom Layer" at 7264.02,3238.66 h60
  text "16" at 5661.16,3114.34 h60
  text "15.00mil (0.381mm)" at 5993.16,3114.34 h60
  text "PTH" at 6629.72,3114.34 h60
  text "Round" at 6888.86,3114.34 h60
  text "Top Layer - Bottom Layer" at 7264.02,3114.34 h60
  text "4" at 5661.16,2990.02 h60
  text "25.59mil (0.650mm)" at 5993.16,2990.02 h60
  text "PTH" at 6629.72,2990.02 h60
  text "Round" at 6888.86,2990.02 h60
  text "Top Layer - Bottom Layer" at 7264.02,2990.02 h60
  text "3" at 5661.16,2865.7 h60
  text "33.46mil (0.850mm)" at 5993.16,2865.7 h60
  text "PTH" at 6629.72,2865.7 h60
  text "Round" at 6888.86,2865.7 h60
  text "Top Layer - Bottom Layer" at 7264.02,2865.7 h60
  text "16" at 5661.16,2741.38 h60
  text "40.00mil (1.016mm)" at 5993.16,2741.38 h60
  text "PTH" at 6629.72,2741.38 h60
  text "Round" at 6888.86,2741.38 h60
  text "Top Layer - Bottom Layer" at 7264.02,2741.38 h60
  text "2" at 5661.16,2617.06 h60
  text "51.18mil (1.300mm)" at 5993.16,2617.06 h60
  text "PTH" at 6629.72,2617.06 h60
  text "Round" at 6888.86,2617.06 h60
  text "Top Layer - Bottom Layer" at 7264.02,2617.06 h60
  text "105 Total" at 5661.16,2492.74 h60
  text ".Layer_Name" at 577,-858.49 h60
M17 Embedded Cavity:
  text ".Layer_Name" at 577,-858.49 h60
M18 Embedded Assembly:
  text ".Layer_Name" at 577,-858.49 h60
M19 Embedded Keepout:
  text ".Layer_Name" at 577,-858.49 h60

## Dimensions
0,-400 to 1000,-400 on M2 Board Dimensions
0,0 to 0,1250 on M2 Board Dimensions
2200,0 to 2200,0 on M2 Board Dimensions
